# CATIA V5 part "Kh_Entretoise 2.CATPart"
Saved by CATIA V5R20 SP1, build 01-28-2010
Part number: Entretoise 2
Bounding box of the stored display mesh (mm): x 0 to 34, y -10.5 to 10.5, z -10.5 to 10.5
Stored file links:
  G:\Khaled_CFAO_2011\SIL\SIL_GR1\tmerino\Khaled\CAD_Thinkmotion\Kh_Entretoise 2.CATPart
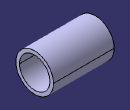
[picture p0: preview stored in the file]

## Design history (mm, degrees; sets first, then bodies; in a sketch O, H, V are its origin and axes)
Body1 (main body)
  Sketch1 on yz-plane, origin (0, 0, 0), H (0, 1, 0), V (0, 0, 1)
    circle A1 centre (0, 0) radius 8.5
    circle A2 centre (0, 0) radius 10.5
    radius A1 = 8.5
    radius A2 = 10.5
  Pad1: profile Sketch1, direction (1, 0, 0), length 34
